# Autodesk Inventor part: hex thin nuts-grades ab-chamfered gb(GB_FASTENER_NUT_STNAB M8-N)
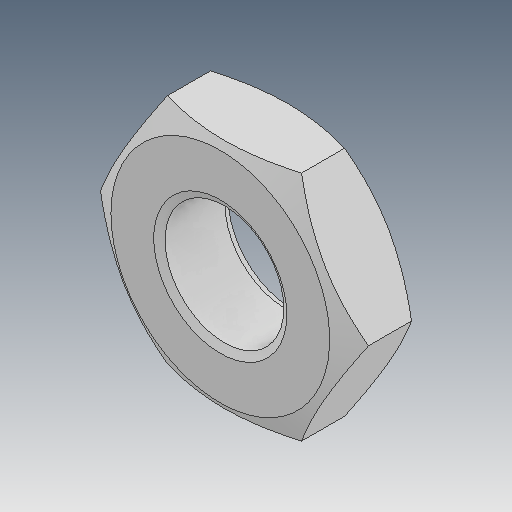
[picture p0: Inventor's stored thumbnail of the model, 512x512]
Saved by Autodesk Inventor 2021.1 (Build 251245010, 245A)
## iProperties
Created: 2019-05
Part Number: hex thin nuts-grades ab-chamfered gb(GB_FASTENER_NUT_STNAB M8-N)
Material: Ogólny
Document SubType Name: Modeling
Designer: user
Density: 1 g/cm^3
Appearance: Domyślna
Author: user
Revision Number: ÈÎºÎ
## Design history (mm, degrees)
feature "ÊäÈë1"
node "Bryła1"
